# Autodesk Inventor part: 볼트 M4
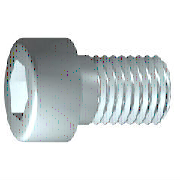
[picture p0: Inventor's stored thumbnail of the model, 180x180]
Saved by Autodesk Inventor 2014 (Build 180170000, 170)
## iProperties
IsCustomPart: 1
Created: 2012-02
Part Number: 볼트 M4
Material: 강철, 연강
Description: 6각머리 태핑 나사
Document SubType Name: Modeling
Standard: KS B 1003
Designer: mduedu
Standards Organization: KS
Language: ko-KR
Size Designation: M 4 x 10
Categories: <MemberInstance><Categories><Category DisplayName="조임쇠" InternalName="e4da775c-781d-43d5-af7c-5136215cf5a6" Mnemonic="FSTN"><Category DisplayName="볼트" InternalN
Density: 1 g/cm^3
Appearance: 강철
Author: mduedu
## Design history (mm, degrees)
sketch "스케치1"
  geometry: L1 (-1, 0)-(10, 0); L2 (10, 0)-(10, 2); L3 (10, 2)-(1.75, 2); L4 (1.75, 2)-(1.32, 2); L5 (1.32, 2)-(0, 2); L6 (0, 2)-(0, 3.5); L7 (0, 3.5)-(-4, 3.5); L8 (-4, 3.5)-(-4, 1.732); L9 (-4, 1.732)-(-2, 1.732); L10 (-2, 1.732)-(-1, 0); L11 (-6.8, 0)-(12.8, 0) reference; L12 (0, -0.7)-(0, 4.2) reference; L13 (1.75, 2)-(0, 2)
  constraints: 22 end point, 6 parallel, 2 collinear, 2 perpendicular, 1 horizontal, 1 point on line
  dimensions: "d1" = 8.25 distance from line of L3.end L2 (= GEL); "d2" = 0.42952 distance of L4.end L3.end (computed from GAL); "d3" = 4 distance between parallel lines of L8 L6 (= KOH); "d4" = 2 distance of L8.end L9.end (= INTI); "d5" = 60 deg angle of L10 L1; "d6" = 4 diameter of L3 L1 (= GD); "d7" = 4 diameter of L5 L1 (= BDM); "d8" = 3.4641 diameter of L9 L1 (= 1.1547 x SW); "d9" = 7 diameter of L7 L1 (= KOD); "d26" = 10 distance between parallel lines of L12 L2 (= NLG)
revolve "본체" sketch "스케치1" stored, may be unused: angle "d10" = 90 deg
sketch "스케치2"
  geometry: L1 (0, -4.9)-(0, 4.9) reference; L2 (-4.9, 0)-(4.9, 0) reference; L3 (1.732, 0)-(0.866, -1.5); L4 (0.866, -1.5)-(-0.866, -1.5); L5 (-0.866, -1.5)-(-1.732, 0); L6 (-1.732, 0)-(-0.866, 1.5); L7 (-0.866, 1.5)-(0.866, 1.5); L8 (0.866, 1.5)-(1.732, 0); 2 further points
  constraints: 12 end point, 1 coincident, 1 horizontal alignment, 1 point on line, 12 other
extrude "슬롯" join sketch "스케치2" stored distance "d11" = 10; taper "d12" = 0 deg
workplane "Work Plane1"
fillet "Fillet2" dims "d30" = 0.1 (= R)
body "Solid1"
fillet "모깎기1" dims "d17" = 0.4 (= RR)
feature "스레드" dims "d13" = 8.25 (= GEL), "d14" = 0
chamfer "모따기1" distance "d15" = 0.42941 (= -0.5 x SPD + 0.5 x GD); stored, may be unused: second distance "d16" = 0.42941 (= GUL), angle "d27" = 45 deg
other parameters: "GD" = 4 (= NND) [user parameter; used in 2 equation terms], "NLG" = 10 [user parameter; used in 1 equation term], "GEL" = 8.25 [user parameter; used in 2 equation terms], "KOD" = 7 [user parameter; used in 1 equation term], "KOH" = 4 [user parameter; used in 1 equation term], "INTI" = 2 [user parameter; used in 1 equation term], "GAL" = 0.42941 (= 0.61345 x PTC) [user parameter; used in 1 equation term], "GUL" = 0.42941 (= 0.61345 x PTC) [user parameter; used in 1 equation term], "BDM" = 4 (= NND) [user parameter; used in 1 equation term], "SW" = 3 [user parameter; used in 2 equation terms], "RR" = 0.4 [user parameter; used in 1 equation term], "SPD" = 3.14117 (= NND - 1.2269 x PTC) [user parameter; used in 1 equation term], "d19" = 0, "d28" = 0, "d29" = 0, "R" = 0.1 [user parameter; used in 1 equation term], "PHH" = 0.2 [user parameter], "GD1" = 3.14117 (= THREADDIA - 1.2269 x PTC) [user parameter], "THREADDIA" = 4 [user parameter; used in 1 equation term], "FAWI" = 45 deg [user parameter], "TPU" = 14.28571 (computed from PTC) [user parameter], "PTC" = 0.7 [user parameter; used in 5 equation terms], "NND" = 4 [user parameter; used in 3 equation terms], "TOA" = 30 deg [user parameter], "E0" = 3.465 (= 1.155 x SW) [user parameter]
